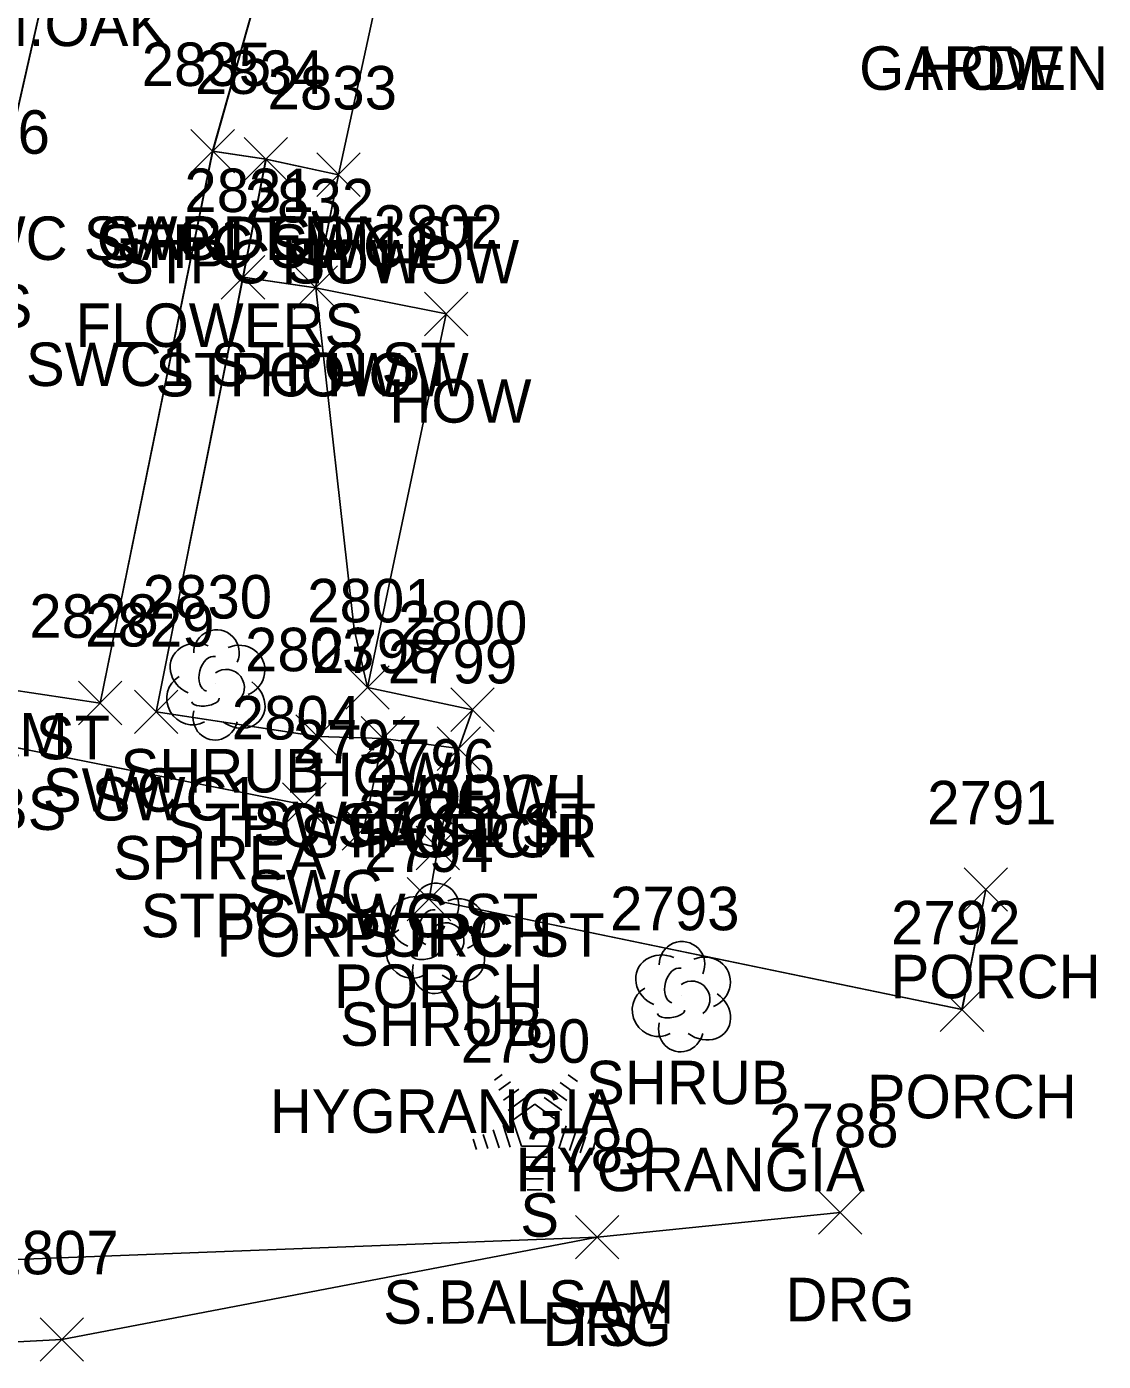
# Model space of a CAD drawing. Extents: x 1554668 to 1563881, y 831386 to 834374.
# Drawn here: x 1562289.6 to 1562339.1, y 832623.4 to 832684.7 of the extents above; entities that cross this region are included whole.
import ezdxf

# ---------------------------------------------------------------- set-up
doc = ezdxf.new("R2010")
doc.units = 0
for name, color, linetype in [('L_A', 7, 'Continuous'), ('L_C', 7, 'Continuous'), ('L_I', 7, 'Continuous'), ('L_TIC', 7, 'Continuous'), ('LAPB', 7, 'Continuous'), ('LBC', 7, 'Continuous'), ('LBF', 7, 'Continuous'), ('LELB', 7, 'Continuous'), ('LSH', 7, 'Continuous'), ('LTC', 7, 'Continuous'), ('R_A', 7, 'Continuous'), ('R_C', 7, 'Continuous'), ('R_I', 7, 'Continuous'), ('R_TIC', 7, 'Continuous'), ('RDG', 7, 'Continuous'), ('RSW', 7, 'Continuous')]:
    doc.layers.add(name, color=color, linetype=linetype)

msp = doc.modelspace()

# ---------------------------------------------------------------- linework, layer by layer
at = {"layer": 'L_TIC'}
for points in [[(1562297.126, 832678.008), (1562299.126, 832680.008)], [(1562299.126, 832678.008), (1562297.126, 832680.008)], [(1562299.574, 832677.643), (1562301.574, 832679.643)], [(1562301.574, 832677.643), (1562299.574, 832679.643)], [(1562302.912, 832676.929), (1562304.912, 832678.929)], [(1562304.912, 832676.929), (1562302.912, 832678.929)], [(1562302.912, 832676.929), (1562304.912, 832678.929)], [(1562304.912, 832676.929), (1562302.912, 832678.929)], [(1562298.52, 832672.211), (1562300.52, 832674.211)], [(1562300.52, 832672.211), (1562298.52, 832674.211)], [(1562301.862, 832671.734), (1562303.862, 832673.734)], [(1562303.862, 832671.734), (1562301.862, 832673.734)], [(1562301.862, 832671.734), (1562303.862, 832673.734)], [(1562303.862, 832671.734), (1562301.862, 832673.734)], [(1562307.865, 832670.526), (1562309.865, 832672.526)], [(1562309.865, 832670.526), (1562307.865, 832672.526)], [(1562304.246, 832653.343), (1562306.246, 832655.343)], [(1562306.246, 832653.343), (1562304.246, 832655.343)], [(1562309.072, 832652.327), (1562311.072, 832654.327)], [(1562311.072, 832652.327), (1562309.072, 832654.327)], [(1562309.072, 832652.327), (1562311.072, 832654.327)], [(1562311.072, 832652.327), (1562309.072, 832654.327)], [(1562304.96, 832651.009), (1562306.96, 832653.009)], [(1562306.96, 832651.009), (1562304.96, 832653.009)], [(1562308.445, 832650.537), (1562310.445, 832652.537)], [(1562310.445, 832650.537), (1562308.445, 832652.537)], [(1562308.445, 832650.537), (1562310.445, 832652.537)], [(1562310.445, 832650.537), (1562308.445, 832652.537)], [(1562304.077, 832646.86), (1562306.077, 832648.86)], [(1562306.077, 832646.86), (1562304.077, 832648.86)], [(1562307.476, 832645.968), (1562309.476, 832647.968)], [(1562309.476, 832645.968), (1562307.476, 832647.968)], [(1562307.476, 832645.968), (1562309.476, 832647.968)], [(1562309.476, 832645.968), (1562307.476, 832647.968)], [(1562332.669, 832644.054), (1562334.669, 832646.054)], [(1562334.669, 832644.054), (1562332.669, 832646.054)], [(1562307.074, 832643.61), (1562309.074, 832645.61)], [(1562309.074, 832643.61), (1562307.074, 832645.61)], [(1562331.574, 832638.535), (1562333.574, 832640.535)], [(1562333.574, 832638.535), (1562331.574, 832640.535)], [(1562314.801, 832628.068), (1562316.801, 832630.068)], [(1562316.801, 832628.068), (1562314.801, 832630.068)]]:
    msp.add_lwpolyline(points, dxfattribs=at)
at = {"layer": 'LAPB'}
for points in [[(1562298.126, 832679.008), (1562303.207, 832697.006), (1562306.648, 832696.406), (1562307.037, 832692.317)], [(1562298.129, 832679.008), (1562303.209, 832697.006), (1562306.65, 832696.404), (1562307.042, 832692.318)], [(1562298.129, 832679.008), (1562303.209, 832697.006), (1562306.65, 832696.404), (1562307.042, 832692.318)], [(1562298.129, 832679.008), (1562303.209, 832697.006), (1562306.65, 832696.404), (1562307.042, 832692.318)]]:
    msp.add_lwpolyline(points, dxfattribs=at)
at = {"layer": 'LBC'}
for points in [[(1562310.072, 832653.327), (1562305.246, 832654.343), (1562308.865, 832671.526), (1562302.862, 832672.734), (1562303.912, 832677.929), (1562307.037, 832692.317)], [(1562310.072, 832653.326), (1562305.246, 832654.342), (1562304.639, 832657.022), (1562302.868, 832672.734), (1562303.915, 832677.928), (1562307.042, 832692.318)], [(1562310.072, 832653.326), (1562305.246, 832654.342), (1562304.639, 832657.022), (1562302.868, 832672.734), (1562303.915, 832677.928), (1562307.042, 832692.318)], [(1562310.072, 832653.326), (1562305.246, 832654.342), (1562304.639, 832657.022), (1562302.868, 832672.734), (1562303.915, 832677.928), (1562307.042, 832692.318)]]:
    msp.add_lwpolyline(points, dxfattribs=at)
at = {"layer": 'LBF'}
for points in [[(1562303.912, 832677.929), (1562300.574, 832678.643)], [(1562303.915, 832677.928), (1562300.582, 832678.645)], [(1562303.915, 832677.928), (1562300.582, 832678.645)], [(1562303.915, 832677.928), (1562300.582, 832678.645)], [(1562299.52, 832673.211), (1562302.862, 832672.734)], [(1562299.524, 832673.211), (1562302.868, 832672.734)], [(1562299.524, 832673.211), (1562302.868, 832672.734)], [(1562299.524, 832673.211), (1562302.868, 832672.734)], [(1562333.669, 832645.054), (1562332.574, 832639.535), (1562308.074, 832644.61), (1562308.476, 832646.968), (1562309.445, 832651.537), (1562310.072, 832653.327)], [(1562333.67, 832645.054), (1562332.575, 832639.535), (1562308.077, 832644.61), (1562308.477, 832646.967), (1562309.451, 832651.536), (1562310.072, 832653.326)], [(1562333.67, 832645.054), (1562332.575, 832639.535), (1562308.077, 832644.61), (1562308.477, 832646.967), (1562309.451, 832651.536), (1562310.072, 832653.326)], [(1562333.67, 832645.054), (1562332.575, 832639.535), (1562308.077, 832644.61), (1562308.477, 832646.967), (1562309.451, 832651.536), (1562310.072, 832653.326)], [(1562308.476, 832646.968), (1562305.077, 832647.86), (1562305.96, 832652.009), (1562309.445, 832651.537)], [(1562308.477, 832646.967), (1562305.082, 832647.859), (1562305.961, 832652.008), (1562309.451, 832651.536)], [(1562308.477, 832646.967), (1562305.082, 832647.859), (1562305.961, 832652.008), (1562309.451, 832651.536)], [(1562308.477, 832646.967), (1562305.082, 832647.859), (1562305.961, 832652.008), (1562309.451, 832651.536)]]:
    msp.add_lwpolyline(points, dxfattribs=at)
at = {"layer": 'LELB'}
for points in [[(1562282.332, 832656.045), (1562284.68, 832660.182), (1562288.013, 832675.892), (1562295.711, 832709.979), (1562299.266, 832748.574)], [(1562282.333, 832656.044), (1562284.684, 832660.181), (1562288.016, 832675.892), (1562295.713, 832709.976), (1562299.269, 832748.573)], [(1562282.333, 832656.044), (1562284.684, 832660.181), (1562288.016, 832675.892), (1562295.713, 832709.976), (1562299.269, 832748.573)], [(1562282.333, 832656.044), (1562284.684, 832660.181), (1562288.016, 832675.892), (1562295.713, 832709.976), (1562299.269, 832748.573)], [(1562315.801, 832629.068), (1562286.708, 832627.946), (1562278.326, 832627.794), (1562281.593, 832652.354)], [(1562315.801, 832629.068), (1562286.708, 832627.946), (1562278.327, 832627.793), (1562281.596, 832652.353)], [(1562315.801, 832629.068), (1562286.708, 832627.946), (1562278.327, 832627.793), (1562281.596, 832652.353)], [(1562315.801, 832629.068), (1562286.708, 832627.946), (1562278.327, 832627.793), (1562281.596, 832652.353)]]:
    msp.add_lwpolyline(points, dxfattribs=at)
at = {"layer": 'LSH'}
for p, q in [((1562298.259, 832654.518), (1562298.259, 832654.518)), ((1562298.259, 832654.518), (1562298.259, 832654.518)), ((1562308.351, 832642.866), (1562308.351, 832642.866)), ((1562308.351, 832642.866), (1562308.351, 832642.866)), ((1562319.659, 832640.183), (1562319.659, 832640.183)), ((1562319.659, 832640.183), (1562319.659, 832640.183))]:
    msp.add_line(p, q, dxfattribs=at)
for centre in [(1562298.305, 832655.952), (1562308.398, 832644.3), (1562319.705, 832641.617)]:
    msp.add_arc(centre, 1.047, 335.52715, 180.95627, dxfattribs=at)
for centre, major_axis, ratio, start_param, end_param in [((1562297.467, 832655.185), (1.21, -0.512), 0.895232, 1.570796, 4.712389), ((1562299.3, 832655.102), (-1.141, -0.483), 0.949671, 1.570796, 4.712389), ((1562298.05, 832654.976), (-0.208, -0.792), 0.645439, 3.141593, 6.283185), ((1562298.759, 832654.351), (-0.5, 0.667), 0.989748, 3.141593, 6.283185), ((1562297.175, 832653.809), (0.584, -1.042), 0.959034, 3.141593, 6.283185), ((1562299.259, 832653.685), (-1.09, 0.792), 0.841452, 1.570796, 4.712389), ((1562297.8, 832653.768), (-0.625, -0.083), 0.423636, 0, 3.141593), ((1562298.259, 832653.018), (0.265, 1.061), 0.942809, 1.570796, 4.712389), ((1562307.559, 832643.532), (1.21, -0.512), 0.895232, 1.570796, 4.712389), ((1562309.392, 832643.449), (-1.141, -0.483), 0.949671, 1.570796, 4.712389), ((1562308.142, 832643.324), (-0.208, -0.792), 0.645439, 3.141593, 6.283185), ((1562308.851, 832642.699), (-0.5, 0.667), 0.989748, 3.141593, 6.283185), ((1562307.268, 832642.157), (0.584, -1.042), 0.959034, 3.141593, 6.283185), ((1562309.351, 832642.033), (-1.09, 0.792), 0.841452, 1.570796, 4.712389), ((1562307.893, 832642.116), (-0.625, -0.083), 0.423636, 0, 3.141593), ((1562318.867, 832640.85), (1.21, -0.512), 0.895232, 1.570796, 4.712389), ((1562320.7, 832640.767), (-1.141, -0.483), 0.949671, 1.570796, 4.712389), ((1562308.351, 832641.366), (0.265, 1.061), 0.942809, 1.570796, 4.712389), ((1562319.45, 832640.641), (-0.208, -0.792), 0.645439, 3.141593, 6.283185), ((1562320.159, 832640.016), (-0.5, 0.667), 0.989748, 3.141593, 6.283185), ((1562318.575, 832639.475), (0.584, -1.042), 0.959034, 3.141593, 6.283185), ((1562320.659, 832639.35), (-1.09, 0.792), 0.841452, 1.570796, 4.712389), ((1562319.2, 832639.433), (-0.625, -0.083), 0.423636, 0, 3.141593), ((1562319.659, 832638.683), (0.265, 1.061), 0.942809, 1.570796, 4.712389)]:
    msp.add_ellipse(centre, major_axis=major_axis, ratio=ratio, start_param=start_param, end_param=end_param, dxfattribs=at)
at = {"layer": 'LTC'}
for p, q in [((1562311.078, 832636.297), (1562311.432, 832636.554)), ((1562314.476, 832636.537), (1562314.895, 832636.233)), ((1562311.287, 832635.831), (1562311.817, 832636.216)), ((1562314.105, 832636.189), (1562314.654, 832635.79)), ((1562311.497, 832635.366), (1562312.201, 832635.877)), ((1562311.707, 832634.9), (1562312.585, 832635.538)), ((1562313.363, 832635.492), (1562314.172, 832634.903)), ((1562313.734, 832635.841), (1562314.413, 832635.347)), ((1562311.931, 832634.445), (1562312.943, 832635.179)), ((1562312.943, 832635.179), (1562313.94, 832634.454)), ((1562311.477, 832634.226), (1562311.807, 832633.206)), ((1562311.931, 832634.445), (1562312.318, 832633.251)), ((1562313.94, 832634.454), (1562313.549, 832633.251)), ((1562314.377, 832634.183), (1562314.039, 832633.144)), ((1562310.11, 832633.576), (1562310.262, 832633.108)), ((1562310.566, 832633.793), (1562310.777, 832633.141)), ((1562311.021, 832634.009), (1562311.292, 832633.174)), ((1562314.822, 832633.933), (1562314.534, 832633.048)), ((1562315.267, 832633.683), (1562315.029, 832632.953)), ((1562313.549, 832633.251), (1562312.318, 832633.251)), ((1562315.711, 832633.433), (1562315.524, 832632.858)), ((1562313.51, 832632.751), (1562312.366, 832632.751)), ((1562313.427, 832632.251), (1562312.438, 832632.251)), ((1562313.343, 832631.751), (1562312.511, 832631.751)), ((1562313.259, 832631.251), (1562312.584, 832631.251))]:
    msp.add_line(p, q, dxfattribs=at)
at = {"layer": 'R_TIC'}
for points in [[(1562297.126, 832678.008), (1562299.126, 832680.008)], [(1562299.126, 832678.008), (1562297.126, 832680.008)], [(1562297.126, 832678.008), (1562299.126, 832680.008)], [(1562299.126, 832678.008), (1562297.126, 832680.008)], [(1562299.574, 832677.643), (1562301.574, 832679.643)], [(1562301.574, 832677.643), (1562299.574, 832679.643)], [(1562298.52, 832672.211), (1562300.52, 832674.211)], [(1562300.52, 832672.211), (1562298.52, 832674.211)], [(1562291.959, 832652.632), (1562293.959, 832654.632)], [(1562293.959, 832652.632), (1562291.959, 832654.632)], [(1562294.53, 832652.232), (1562296.53, 832654.232)], [(1562296.53, 832652.232), (1562294.53, 832654.232)], [(1562301.955, 832651.095), (1562303.955, 832653.095)], [(1562303.955, 832651.095), (1562301.955, 832653.095)], [(1562304.96, 832651.009), (1562306.96, 832653.009)], [(1562306.96, 832651.009), (1562304.96, 832653.009)], [(1562301.34, 832647.956), (1562303.34, 832649.956)], [(1562303.34, 832647.956), (1562301.34, 832649.956)], [(1562304.077, 832646.86), (1562306.077, 832648.86)], [(1562306.077, 832646.86), (1562304.077, 832648.86)], [(1562325.971, 832629.203), (1562327.971, 832631.203)], [(1562327.971, 832629.203), (1562325.971, 832631.203)], [(1562314.801, 832628.068), (1562316.801, 832630.068)], [(1562316.801, 832628.068), (1562314.801, 832630.068)], [(1562290.198, 832623.361), (1562292.198, 832625.361)], [(1562292.198, 832623.361), (1562290.198, 832625.361)]]:
    msp.add_lwpolyline(points, dxfattribs=at)
at = {"layer": 'RDG'}
for points in [[(1562326.971, 832630.203), (1562315.801, 832629.068), (1562291.198, 832624.361), (1562278.67, 832623.702), (1562270.069, 832624.469), (1562265.099, 832626.673), (1562261.428, 832631.195)], [(1562326.975, 832630.202), (1562315.801, 832629.068), (1562291.197, 832624.361), (1562278.676, 832623.701), (1562270.068, 832624.47), (1562265.098, 832626.674), (1562261.43, 832631.195)], [(1562326.975, 832630.202), (1562315.801, 832629.068), (1562291.197, 832624.361), (1562278.676, 832623.701), (1562270.068, 832624.47), (1562265.098, 832626.674), (1562261.43, 832631.195)], [(1562326.975, 832630.202), (1562315.801, 832629.068), (1562291.197, 832624.361), (1562278.676, 832623.701), (1562270.068, 832624.47), (1562265.098, 832626.674), (1562261.43, 832631.195)]]:
    msp.add_lwpolyline(points, dxfattribs=at)
at = {"layer": 'RSW'}
for points in [[(1562305.077, 832647.86), (1562302.34, 832648.956), (1562283.893, 832652.613), (1562282.779, 832652.043), (1562281.593, 832652.354), (1562282.332, 832656.045), (1562283.81, 832655.714), (1562284.388, 832654.916), (1562292.959, 832653.632), (1562298.126, 832679.008)], [(1562305.082, 832647.859), (1562302.34, 832648.955), (1562283.895, 832652.612), (1562282.781, 832652.042), (1562281.596, 832652.353), (1562282.333, 832656.044), (1562283.813, 832655.713), (1562284.387, 832654.914), (1562292.959, 832653.631), (1562298.129, 832679.008)], [(1562305.082, 832647.859), (1562302.34, 832648.955), (1562283.895, 832652.612), (1562282.781, 832652.042), (1562281.596, 832652.353), (1562282.333, 832656.044), (1562283.813, 832655.713), (1562284.387, 832654.914), (1562292.959, 832653.631), (1562298.129, 832679.008)], [(1562305.082, 832647.859), (1562302.34, 832648.955), (1562283.895, 832652.612), (1562282.781, 832652.042), (1562281.596, 832652.353), (1562282.333, 832656.044), (1562283.813, 832655.713), (1562284.387, 832654.914), (1562292.959, 832653.631), (1562298.129, 832679.008)], [(1562305.96, 832652.009), (1562302.955, 832652.095), (1562295.53, 832653.232), (1562299.52, 832673.211), (1562300.574, 832678.643), (1562298.126, 832679.008)], [(1562305.961, 832652.008), (1562302.958, 832652.094), (1562295.535, 832653.232), (1562299.524, 832673.211), (1562300.582, 832678.645), (1562298.129, 832679.008)], [(1562305.961, 832652.008), (1562302.958, 832652.094), (1562295.535, 832653.232), (1562299.524, 832673.211), (1562300.582, 832678.645), (1562298.129, 832679.008)], [(1562305.961, 832652.008), (1562302.958, 832652.094), (1562295.535, 832653.232), (1562299.524, 832673.211), (1562300.582, 832678.645), (1562298.129, 832679.008)]]:
    msp.add_lwpolyline(points, dxfattribs=at)

# ---------------------------------------------------------------- texts
at = {"layer": 'L_A'}
for s, p in [('GARDEN', (1562327.846, 832681.831)), ('HOW', (1562330.563, 832681.831)), ('GARDEN', (1562292.795, 832674.008)), ('STPC SWC1', (1562292.858, 832673.643)), ('STPC ST HOW', (1562293.645, 832672.929)), ('HOW', (1562301.298, 832672.929)), ('TS', (1562286.422, 832670.892)), ('SWC1 STPC ST', (1562289.544, 832668.211)), ('STPC HOW', (1562295.492, 832667.734)), ('HOW', (1562300.247, 832667.734)), ('HOW', (1562306.251, 832666.526)), ('STPC1 SWC TS ST', (1562269.49, 832651.045)), ('SHRUB', (1562293.889, 832649.518)), ('HOW', (1562302.632, 832649.343)), ('PORCH', (1562305.694, 832648.327)), ('HOW', (1562307.457, 832648.327)), ('STPC ST STPC1 ST BS', (1562262.282, 832647.797)), ('STPC ST STPC1 ST BS', (1562262.282, 832647.797)), ('STPC SWC1 ST', (1562295.983, 832647.009)), ('STPC POR', (1562302.146, 832646.537)), ('PORCH', (1562305.068, 832646.537)), ('STPC SWC ST', (1562294.817, 832642.86)), ('POR STPC ST', (1562298.31, 832641.968)), ('PORCH', (1562304.098, 832641.968)), ('PORCH', (1562329.291, 832640.054)), ('PORCH', (1562303.696, 832639.61)), ('SHRUB', (1562303.981, 832637.866)), ('SHRUB', (1562315.288, 832635.183)), ('PORCH', (1562328.196, 832634.535)), ('S', (1562312.268, 832629.089)), ('TS', (1562314.211, 832624.068))]:
    msp.add_text(s, height=2, dxfattribs=at).set_placement(p)
at = {"layer": 'L_C'}
for s, p in [('M.OAK', (1562287.423, 832683.841)), ('M.BALSAM', (1562277.641, 832651.182)), ('SPIREA', (1562293.542, 832645.518)), ('HYGRANGIA', (1562300.752, 832633.866)), ('HYGRANGIA', (1562312.06, 832631.183)), ('S.BALSAM', (1562305.969, 832625.089))]:
    msp.add_text(s, height=2, dxfattribs=at).set_placement(p)
at = {"layer": 'L_I'}
for s, p in [('2835', (1562294.866, 832682.008)), ('2834', (1562297.314, 832681.643)), ('2833', (1562300.652, 832680.929)), ('2833', (1562300.652, 832680.929)), ('2836', (1562284.698, 832678.892)), ('2831', (1562296.827, 832676.211)), ('2832', (1562299.602, 832675.734)), ('2832', (1562299.602, 832675.734)), ('2802', (1562305.526, 832674.526)), ('2830', (1562294.912, 832657.518)), ('2801', (1562302.474, 832657.343)), ('2800', (1562306.646, 832656.327)), ('2800', (1562306.646, 832656.327)), ('2798', (1562302.7, 832655.009)), ('2799', (1562306.178, 832654.537)), ('2799', (1562306.178, 832654.537)), ('2797', (1562301.817, 832650.86)), ('2796', (1562305.161, 832649.968)), ('2796', (1562305.161, 832649.968)), ('2791', (1562330.976, 832648.054)), ('2795', (1562304.814, 832647.61)), ('2794', (1562305.091, 832645.866)), ('2793', (1562316.399, 832643.183)), ('2792', (1562329.314, 832642.535)), ('2790', (1562309.536, 832637.089)), ('2789', (1562312.533, 832632.068))]:
    msp.add_text(s, height=2, dxfattribs=at).set_placement(p)
at = {"layer": 'LTC'}
msp.add_text('.', height=1.037, rotation=270, dxfattribs=at).set_placement((1562312.825, 832634.193))
at = {"layer": 'R_A'}
for s, p in [('SWC SWC1 GDN ST', (1562285.22, 832674.008)), ('SWC SWC1 GDN ST', (1562285.22, 832674.008)), ('STPC SWC1', (1562292.858, 832673.643)), ('SWC1 STPC ST', (1562289.544, 832668.211)), ('STPC1 SWC TS ST', (1562269.49, 832651.045)), ('SWC', (1562290.321, 832648.632)), ('SWC1', (1562292.57, 832648.232)), ('STPC SWC1 ST', (1562295.983, 832647.009)), ('SWC1', (1562299.995, 832647.095)), ('SWC', (1562299.702, 832643.956)), ('STPC SWC ST', (1562294.817, 832642.86)), ('DRG', (1562324.459, 832625.203)), ('DRG', (1562313.289, 832624.068))]:
    msp.add_text(s, height=2, dxfattribs=at).set_placement(p)
at = {"layer": 'R_C'}
msp.add_text('FLOWERS', height=2, dxfattribs=at).set_placement((1562291.827, 832670.008))
msp.add_text('FLOWERS', height=2, dxfattribs=at).set_placement((1562291.827, 832670.008))
at = {"layer": 'R_I'}
for s, p in [('2835', (1562294.866, 832682.008)), ('2835', (1562294.866, 832682.008)), ('2834', (1562297.314, 832681.643)), ('2831', (1562296.827, 832676.211)), ('2828', (1562289.699, 832656.632)), ('2829', (1562292.262, 832656.232)), ('2803', (1562299.617, 832655.095)), ('2798', (1562302.7, 832655.009)), ('2804', (1562299.002, 832651.956)), ('2797', (1562301.817, 832650.86)), ('2788', (1562323.711, 832633.203)), ('2789', (1562312.533, 832632.068)), ('2807', (1562287.86, 832627.361))]:
    msp.add_text(s, height=2, dxfattribs=at).set_placement(p)

doc.saveas('drawing.dxf')
